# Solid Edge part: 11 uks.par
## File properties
Author: Henri
Template: Normal.par
Last saved by: Henri
Revision: 1
Application: Solid Edge
Accuracy: 0,990
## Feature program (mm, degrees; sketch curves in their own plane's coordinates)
sketch for "unnamed Protrusion 1" plane through (0, 0, 0) normal (1, 0, 0) x-axis (0, 1, 0)
  line (-25, -42.5) -> (-25, 40)
  arc centre (-22.5, 40) radius 2.5 from (-25, 40) to (-22.5, 42.5) cw
  line (-22.5, 42.5) -> (22.5, 42.5)
  arc centre (22.5, 40) radius 2.5 from (22.5, 42.5) to (25, 40) cw
  line (25, 40) -> (25, -42.5)
  line (25, -42.5) -> (-25, -42.5)
extrude "unnamed Protrusion 1" add finite 2.5 along +normal
sketch for "unnamed Cutout 1" plane through (2.5, 0, 0) normal (1, 0, 0) x-axis (0, 1, 0)
  line (-15, 26.5) -> (-15, 31)
  arc centre (-13.5, 31) radius 1.5 from (-15, 31) to (-13.5, 32.5) cw
  line (-13.5, 32.5) -> (13.5, 32.5)
  arc centre (13.5, 31) radius 1.5 from (13.5, 32.5) to (15, 31) cw
  line (15, 31) -> (15, 26.5)
  arc centre (13.5, 26.5) radius 1.5 from (13.5, 25) to (15, 26.5) ccw
  line (13.5, 25) -> (-13.5, 25)
  arc centre (-13.5, 26.5) radius 1.5 from (-15, 26.5) to (-13.5, 25) ccw
extrude "unnamed Cutout 1" cut through along -normal
sketch for "ExtrudedCutout_2" #1 plane through (2.5, 0, 0) normal (1, 0, 0) x-axis (0, 1, 0)
  line (14, -5) -> (-14, -5)
  arc centre (-14, -4) radius 1 from (-15, -4) to (-14, -5) ccw
  line (-15, -4) -> (-15, 19)
  arc centre (-14, 19) radius 1 from (-15, 19) to (-14, 20) cw
  line (-14, 20) -> (14, 20)
  arc centre (14, 19) radius 1 from (14, 20) to (15, 19) cw
  line (15, 19) -> (15, -4)
  arc centre (14, -4) radius 1 from (14, -5) to (15, -4) ccw
sketch for "ExtrudedCutout_2" #2 plane through (2.5, 0, 0) normal (1, 0, 0) x-axis (0, 1, 0)
  line (-14, -12.5) -> (14, -12.5)
  arc centre (14, -13.5) radius 1 from (15, -13.5) to (14, -12.5) ccw
  line (15, -13.5) -> (15, -36.5)
  arc centre (14, -36.5) radius 1 from (14, -37.5) to (15, -36.5) ccw
  line (14, -37.5) -> (-14, -37.5)
  arc centre (-14, -36.5) radius 1 from (-15, -36.5) to (-14, -37.5) ccw
  line (-15, -36.5) -> (-15, -13.5)
  arc centre (-14, -13.5) radius 1 from (-15, -13.5) to (-14, -12.5) cw
extrude "ExtrudedCutout_2" cut finite 1 along -normal
sketch for "ExtrudedCutout_3" #1 plane through (0, 0, 0) normal (-1, 0, 0) x-axis (0, -1, 0)
  line (15, -4) -> (15, 19)
  arc centre (14, 19) radius 1 from (15, 19) to (14, 20) ccw
  line (14, 20) -> (-14, 20)
  arc centre (-14, 19) radius 1 from (-14, 20) to (-15, 19) ccw
  line (-15, 19) -> (-15, -4)
  arc centre (-14, -4) radius 1 from (-15, -4) to (-14, -5) ccw
  line (-14, -5) -> (14, -5)
  arc centre (14, -4) radius 1 from (14, -5) to (15, -4) ccw
sketch for "ExtrudedCutout_3" #2 plane through (0, 0, 0) normal (-1, 0, 0) x-axis (0, -1, 0)
  line (15, -36.5) -> (15, -13.5)
  arc centre (14, -13.5) radius 1 from (15, -13.5) to (14, -12.5) ccw
  line (14, -12.5) -> (-14, -12.5)
  arc centre (-14, -13.5) radius 1 from (-14, -12.5) to (-15, -13.5) ccw
  line (-15, -13.5) -> (-15, -36.5)
  arc centre (-14, -36.5) radius 1 from (-14, -37.5) to (-15, -36.5) cw
  line (-14, -37.5) -> (14, -37.5)
  arc centre (14, -36.5) radius 1 from (14, -37.5) to (15, -36.5) ccw
extrude "ExtrudedCutout_3" cut finite 1 along -normal
sketch for "ExtrudedProtrusion_2" plane through (2.5, 0, 0) normal (1, 0, 0) x-axis (0, 1, 0)
  circle centre (20.4236, 0) radius 0.5
extrude "ExtrudedProtrusion_2" add finite 2 along +normal
sketch for "ExtrudedProtrusion_4" plane through (4.5, 20.4236, 0) normal (1, 0, 0) x-axis (0, 1, 0)
  arc centre (-2.4077, -6.4231) radius 7.3595 from (0.1755, 0.4682) to (-6.3062, -0.1809) ccw
  arc centre (-6.0968, -0.6638) radius 0.5264 from (-6.3062, -0.1809) to (-6.4593, -1.0456) ccw
  arc centre (-6.3215, -0.9005) radius 0.2 from (-6.4593, -1.0456) to (-6.1965, -1.0566) ccw
  arc centre (-2.7375, -5.3756) radius 5.5334 from (-6.1965, -1.0566) to (-0.2514, -0.4322) cw
extrude "ExtrudedProtrusion_4" add finite 1 along +normal
fillet "Round_1" radius 0.25
sketch for "ExtrudedProtrusion_7" plane through (0, 0, 0) normal (-1, 0, 0) x-axis (0, -1, 0)
  circle centre (-20.4236, 0) radius 0.5
extrude "ExtrudedProtrusion_7" add finite 2 along +normal
sketch for "ExtrudedProtrusion_8" plane through (-2, 20.4236, 0) normal (-1, 0, 0) x-axis (0, -1, 0)
  arc centre (2.4077, -6.4231) radius 7.3595 from (-0.1755, 0.4682) to (6.3062, -0.1809) cw
  arc centre (6.0968, -0.6638) radius 0.5264 from (6.3062, -0.1809) to (6.4593, -1.0456) cw
  arc centre (6.3215, -0.9005) radius 0.2 from (6.4593, -1.0456) to (6.1965, -1.0566) cw
  arc centre (2.7375, -5.3756) radius 5.5334 from (6.1965, -1.0566) to (0.2514, -0.4322) ccw
extrude "ExtrudedProtrusion_8" add finite 1 along +normal
fillet "Round_3" radius 0.25
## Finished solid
Body 1: solid body, 85 faces, 205 edges, 128 vertices.
  Faces by surface: plane 34, cylinder 32, torus 15, blend 4
  Edges by curve: line 104, circle 83, intersection 18
Bounding box of the edges (mm; curved faces can reach further): 8.500 x 50.000 x 85.000, from (-3, -25, -42.5) to (5.5, 25, 42.5).
Cylindrical faces by radius (mm): R0.2 x2, R0.5 x2, R0.5264 x2, R1 x16, R1.5 x4, R2.5 x2, R5.5334 x2, R7.3595 x2
Toroidal faces (ring radius, tube radius in mm): R0.25 r0.25 x2, R0.2764 r0.25 x4, R0.75 r0.25 x1, R5.7834 r0.25 x4, R7.1095 r0.25 x4
Planar faces by outward normal: +x 5, +y 6, +z 6, -x 5, -y 6, -z 6
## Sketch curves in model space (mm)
arc centre (-2, 14.3269, -0.6638) radius 0.5264 from (-2, 14.1175, -0.1809) through (-2, 13.806, -0.5876) to (-2, 13.9644, -1.0456)
arc centre (-2, 14.1021, -0.9005) radius 0.2 from (-2, 13.9644, -1.0456) through (-2, 14.0937, -1.1004) to (-2, 14.2271, -1.0566)
arc centre (-2, 17.6861, -5.3756) radius 5.5334 from (-2, 14.2271, -1.0566) through (-2, 17.1081, 0.1275) to (-2, 20.1722, -0.4322)
arc centre (-2, 20.4236, 0) radius 0.5 from (-2, 20.5991, 0.4682) through (-2, 20.8689, -0.2275) to (-2, 20.1722, -0.4322)
arc centre (-2, 18.0159, -6.4231) radius 7.3595 from (-2, 20.5991, 0.4682) through (-2, 17.2826, 0.8998) to (-2, 14.1175, -0.1809)
circle centre (0, 20.4236, 0) radius 0.5
arc centre (4.5, 14.3269, -0.6638) radius 0.5264 from (4.5, 14.1175, -0.1809) through (4.5, 13.806, -0.5876) to (4.5, 13.9644, -1.0456)
arc centre (4.5, 14.1021, -0.9005) radius 0.2 from (4.5, 13.9644, -1.0456) through (4.5, 14.0937, -1.1004) to (4.5, 14.2271, -1.0566)
arc centre (4.5, 17.6861, -5.3756) radius 5.5334 from (4.5, 14.2271, -1.0566) through (4.5, 17.1081, 0.1275) to (4.5, 20.1722, -0.4322)
arc centre (4.5, 20.4236, 0) radius 0.5 from (4.5, 20.5991, 0.4682) through (4.5, 20.8689, -0.2275) to (4.5, 20.1722, -0.4322)
arc centre (4.5, 18.0159, -6.4231) radius 7.3595 from (4.5, 20.5991, 0.4682) through (4.5, 17.2826, 0.8998) to (4.5, 14.1175, -0.1809)
circle centre (2.5, 20.4236, 0) radius 0.5
arc centre (0, 14, -4) radius 1 from (0, 15, -4) through (0, 14.6862, -4.7274) to (0, 14, -5)
line (0, 14, -5) -> (0, -14, -5)
arc centre (0, -14, -4) radius 1 from (0, -14, -5) through (0, -14.7274, -4.6862) to (0, -15, -4)
line (0, -15, -4) -> (0, -15, 19)
arc centre (0, -14, 19) radius 1 from (0, -15, 19) through (0, -14.6862, 19.7274) to (0, -14, 20)
line (0, -14, 20) -> (0, 14, 20)
arc centre (0, 14, 19) radius 1 from (0, 14, 20) through (0, 14.7274, 19.6862) to (0, 15, 19)
line (0, 15, 19) -> (0, 15, -4)
arc centre (0, 14, -36.5) radius 1 from (0, 14, -37.5) through (0, 14.7274, -37.1862) to (0, 15, -36.5)
line (0, 14, -37.5) -> (0, -14, -37.5)
arc centre (0, -14, -36.5) radius 1 from (0, -14, -37.5) through (0, -14.7274, -37.1862) to (0, -15, -36.5)
line (0, -15, -36.5) -> (0, -15, -13.5)
arc centre (0, -14, -13.5) radius 1 from (0, -15, -13.5) through (0, -14.6862, -12.7726) to (0, -14, -12.5)
line (0, -14, -12.5) -> (0, 14, -12.5)
arc centre (0, 14, -13.5) radius 1 from (0, 14, -12.5) through (0, 14.7274, -12.8138) to (0, 15, -13.5)
line (0, 15, -13.5) -> (0, 15, -36.5)
arc centre (2.5, 13.5, 31) radius 1.5 from (2.5, 13.5, 32.5) through (2.5, 14.5911, 32.0294) to (2.5, 15, 31)
line (2.5, 15, 31) -> (2.5, 15, 26.5)
arc centre (2.5, 13.5, 26.5) radius 1.5 from (2.5, 13.5, 25) through (2.5, 14.5911, 25.4706) to (2.5, 15, 26.5)
line (2.5, 13.5, 25) -> (2.5, -13.5, 25)
arc centre (2.5, -13.5, 26.5) radius 1.5 from (2.5, -15, 26.5) through (2.5, -14.5294, 25.4089) to (2.5, -13.5, 25)
line (2.5, -15, 26.5) -> (2.5, -15, 31)
arc centre (2.5, -13.5, 31) radius 1.5 from (2.5, -15, 31) through (2.5, -14.5294, 32.0911) to (2.5, -13.5, 32.5)
line (2.5, -13.5, 32.5) -> (2.5, 13.5, 32.5)
arc centre (2.5, 14, 19) radius 1 from (2.5, 14, 20) through (2.5, 14.7274, 19.6862) to (2.5, 15, 19)
line (2.5, 15, 19) -> (2.5, 15, -4)
arc centre (2.5, 14, -4) radius 1 from (2.5, 14, -5) through (2.5, 14.7274, -4.6862) to (2.5, 15, -4)
line (2.5, 14, -5) -> (2.5, -14, -5)
arc centre (2.5, -14, -4) radius 1 from (2.5, -15, -4) through (2.5, -14.6862, -4.7274) to (2.5, -14, -5)
line (2.5, -15, -4) -> (2.5, -15, 19)
arc centre (2.5, -14, 19) radius 1 from (2.5, -15, 19) through (2.5, -14.6862, 19.7274) to (2.5, -14, 20)
line (2.5, -14, 20) -> (2.5, 14, 20)
arc centre (2.5, 14, -13.5) radius 1 from (2.5, 15, -13.5) through (2.5, 14.6862, -12.7726) to (2.5, 14, -12.5)
line (2.5, 15, -13.5) -> (2.5, 15, -36.5)
arc centre (2.5, 14, -36.5) radius 1 from (2.5, 14, -37.5) through (2.5, 14.7274, -37.1862) to (2.5, 15, -36.5)
line (2.5, 14, -37.5) -> (2.5, -14, -37.5)
arc centre (2.5, -14, -36.5) radius 1 from (2.5, -15, -36.5) through (2.5, -14.6862, -37.2274) to (2.5, -14, -37.5)
line (2.5, -15, -36.5) -> (2.5, -15, -13.5)
arc centre (2.5, -14, -13.5) radius 1 from (2.5, -15, -13.5) through (2.5, -14.6862, -12.7726) to (2.5, -14, -12.5)
line (2.5, -14, -12.5) -> (2.5, 14, -12.5)
arc centre (0, 22.5, 40) radius 2.5 from (0, 22.5, 42.5) through (0, 24.3184, 41.7156) to (0, 25, 40)
line (0, 25, 40) -> (0, 25, -42.5)
line (0, 25, -42.5) -> (0, -25, -42.5)
line (0, -25, -42.5) -> (0, -25, 40)
arc centre (0, -22.5, 40) radius 2.5 from (0, -25, 40) through (0, -24.2156, 41.8184) to (0, -22.5, 42.5)
line (0, -22.5, 42.5) -> (0, 22.5, 42.5)
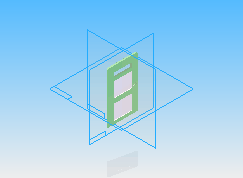
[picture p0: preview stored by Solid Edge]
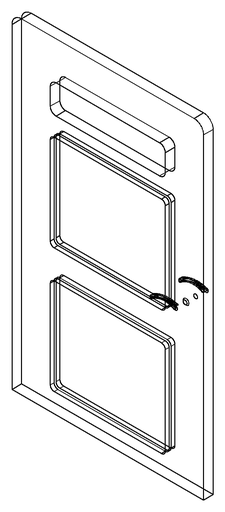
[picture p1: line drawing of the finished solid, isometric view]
